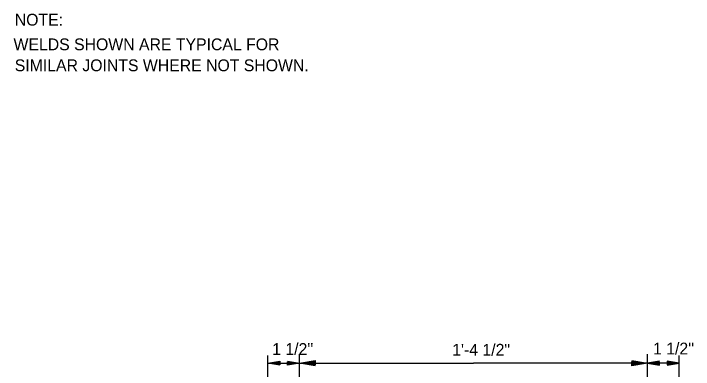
# Model space of a CAD drawing. Extents: x 0.1 to 13.5, y 0.1 to 9.5.
# Drawn here: x 6.676 to 9.362, y 3.771 to 5.175 of the extents above; entities that cross this region are included whole.
import ezdxf

# ---------------------------------------------------------------- set-up
doc = ezdxf.new("R2010")
doc.units = 0
for name, color, linetype in [('Level 2', 7, 'Continuous'), ('Level 3', 7, 'Continuous'), ('Level 50', 7, 'Continuous')]:
    doc.layers.add(name, color=color, linetype=linetype)

msp = doc.modelspace()

# ---------------------------------------------------------------- linework, layer by layer
at = {"layer": 'Level 2'}
for p, q in [((7.6808, 3.7951), (7.8058, 3.7951)), ((7.8058, 3.7951), (8.4933, 3.7951)), ((9.1808, 3.7951), (8.4933, 3.7951)), ((9.3058, 3.7951), (9.1808, 3.7951))]:
    msp.add_line(p, q, dxfattribs=at)
at = {"layer": 'Level 3'}
for p, q in [((7.6808, 3.4864), (7.6808, 3.8259)), ((7.8058, 3.4618), (7.8058, 3.8312)), ((9.1808, 3.4618), (9.1808, 3.8312)), ((9.3058, 3.4864), (9.3058, 3.8259)), ((7.6808, 3.7951), (7.6808, 3.7951)), ((7.6938, 3.7951), (7.6938, 3.7951)), ((7.7928, 3.7951), (7.7928, 3.7951)), ((7.8058, 3.7951), (7.8058, 3.7951)), ((9.1808, 3.7951), (9.1808, 3.7951)), ((9.1938, 3.7951), (9.1938, 3.7951)), ((9.2928, 3.7951), (9.2928, 3.7951)), ((9.3058, 3.7951), (9.3058, 3.7951))]:
    msp.add_line(p, q, dxfattribs=at)
for points in [[(7.7275, 3.7874), (7.6808, 3.7951), (7.7275, 3.8029), (7.7275, 3.7896), (7.6938, 3.7951), (7.7255, 3.8004), (7.7255, 3.7919), (7.7063, 3.7951), (7.7235, 3.7979), (7.7235, 3.7944), (7.7193, 3.7951)], [(7.759, 3.8029), (7.8058, 3.7951), (7.759, 3.7874), (7.759, 3.8006), (7.7928, 3.7951), (7.761, 3.7899), (7.761, 3.7984), (7.7803, 3.7951), (7.763, 3.7924), (7.763, 3.7959), (7.7673, 3.7951)], [(9.2275, 3.8029), (9.1808, 3.7951), (9.2275, 3.7874), (9.2275, 3.8006), (9.1938, 3.7951), (9.2255, 3.7899), (9.2255, 3.7984), (9.2063, 3.7951), (9.2235, 3.7924), (9.2235, 3.7959), (9.2193, 3.7951)], [(9.259, 3.7874), (9.3058, 3.7951), (9.259, 3.8029), (9.259, 3.7896), (9.2928, 3.7951), (9.261, 3.8004), (9.261, 3.7919), (9.2803, 3.7951), (9.263, 3.7979), (9.263, 3.7944), (9.2673, 3.7951)]]:
    msp.add_lwpolyline(points, dxfattribs=at)
at = {"layer": 'Level 50'}
for p, q in [((7.8058, 3.7951), (7.8058, 3.7951)), ((7.8231, 3.7951), (7.8231, 3.7951)), ((9.1634, 3.7951), (9.1634, 3.7951)), ((9.1808, 3.7951), (9.1808, 3.7951))]:
    msp.add_line(p, q, dxfattribs=at)
for points in [[(7.8681, 3.7848), (7.8058, 3.7951), (7.8681, 3.8055), (7.8681, 3.7878), (7.8231, 3.7951), (7.8654, 3.8021), (7.8654, 3.7908), (7.8398, 3.7951), (7.8628, 3.7988), (7.8628, 3.7941), (7.8571, 3.7951)], [(9.1184, 3.8055), (9.1808, 3.7951), (9.1184, 3.7848), (9.1184, 3.8025), (9.1634, 3.7951), (9.1211, 3.7881), (9.1211, 3.7995), (9.1468, 3.7951), (9.1238, 3.7915), (9.1238, 3.7961), (9.1294, 3.7951)]]:
    msp.add_lwpolyline(points, dxfattribs=at)

# ---------------------------------------------------------------- texts
at = {"layer": 'Level 3'}
for s, height, p in [('NOTE:', 0.04667, (6.6808, 5.1281)), ('WELDS SHOWN ARE TYPICAL FOR', 0.046667, (6.6759, 5.0308)), ('SIMILAR JOINTS WHERE NOT SHOWN.', 0.046667, (6.6808, 4.948)), ("1 1/2''", 0.04667, (7.6978, 3.828)), ('1\'-4 1/2"', 0.04667, (8.4091, 3.8251)), ("1 1/2''", 0.04667, (9.2026, 3.8299))]:
    msp.add_text(s, height=height, dxfattribs=at).set_placement(p)

doc.saveas('drawing.dxf')
